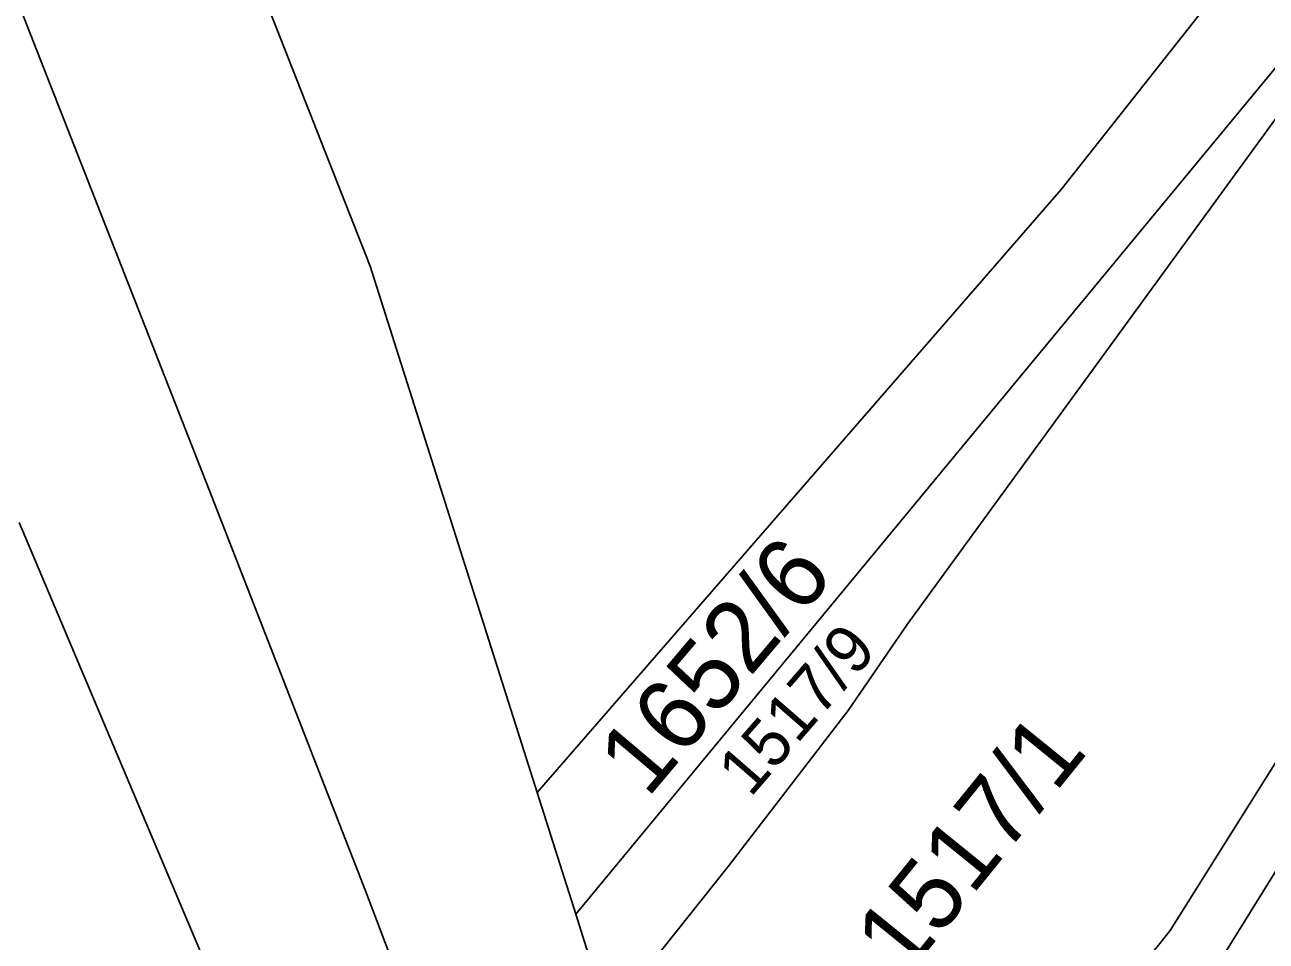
# Model space of a CAD drawing. Extents: x -553916 to -552953, y -1067470 to -1066637.
# Drawn here: x -553527.29 to -553497.63, y -1066969.15 to -1066947.27 of the extents above; entities that cross this region are included whole.
import ezdxf

# ---------------------------------------------------------------- set-up
doc = ezdxf.new("R2010")
doc.units = 0
for name, color, linetype in [('Hranice parcel', 7, 'Continuous'), ('Kolej', 7, 'Continuous'), ('Parcelní čísla', 7, 'Continuous'), ('Vrstva 1', 7, 'Continuous')]:
    doc.layers.add(name, color=color, linetype=linetype)

msp = doc.modelspace()

# ---------------------------------------------------------------- linework, layer by layer
at = {"layer": 'Hranice parcel'}
for p, q in [((-553514.13, -1066968.51), (-553489.9, -1066939.2)), ((-553486.47, -1066947.45), (-553499.93, -1066968.9)), ((-553499.93, -1066968.9), (-553506.23, -1066976.75))]:
    msp.add_line(p, q, dxfattribs=at)
for points in [[(-553515.05, -1066965.6), (-553502.53, -1066951.2), (-553486.22, -1066930.56), (-553479.63, -1066908.8), (-553477.16, -1066903.7)], [(-553489.9, -1066939.2), (-553506.21, -1066961.59), (-553507.62, -1066963.64), (-553510.49, -1066967.37), (-553513.35, -1066970.96)], [(-553481.25, -1066991.64), (-553501.02, -1066983.66), (-553503.13, -1066976.7), (-553485.37, -1066948.09)]]:
    msp.add_lwpolyline(points, dxfattribs=at)
at = {"layer": 'Kolej'}
msp.add_lwpolyline([(-553503.324, -1067065.808), (-553502.678, -1067054.027), (-553502.762, -1067041.504), (-553503.626, -1067029.057), (-553504.756, -1067019.974), (-553506.183, -1067011.388), (-553508.328, -1067001.388), (-553510.948, -1066991.622), (-553512.921, -1066985.291), (-553515.647, -1066977.347), (-553517.422, -1066972.53), (-553519.157, -1066967.95), (-553522.886, -1066958.375), (-553529.101, -1066942.549), (-553538.686, -1066918.107), (-553542.908, -1066907.329), (-553546.692, -1066897.676), (-553555.025, -1066876.441), (-553564.644, -1066851.894), (-553574.241, -1066827.427), (-553583.19, -1066804.618)], dxfattribs=at)
at = {"layer": 'Vrstva 1'}
for p, q in [((-553515.05, -1066965.6), (-553514.13, -1066968.51)), ((-553514.13, -1066968.51), (-553513.35, -1066970.96))]:
    msp.add_line(p, q, dxfattribs=at)
for points in [[(-553537.18, -1066906.98), (-553519.04, -1066953.03), (-553515.05, -1066965.6)], [(-553521.68, -1066973.05), (-553522.23, -1066971.46), (-553527.43, -1066959.15)]]:
    msp.add_lwpolyline(points, dxfattribs=at)

# ---------------------------------------------------------------- texts
at = {"layer": 'Parcelní čísla'}
for s, height, rotation, p in [('1652/6', 1.7, 49.8322, (-553512.418, -1066965.759)), ('1517/9', 1.14, 49, (-553509.959, -1066965.739)), ('1517/1', 1.7, 51, (-553506.254, -1066970.044))]:
    msp.add_text(s, height=height, rotation=rotation, dxfattribs=at).set_placement(p)

doc.saveas('drawing.dxf')
